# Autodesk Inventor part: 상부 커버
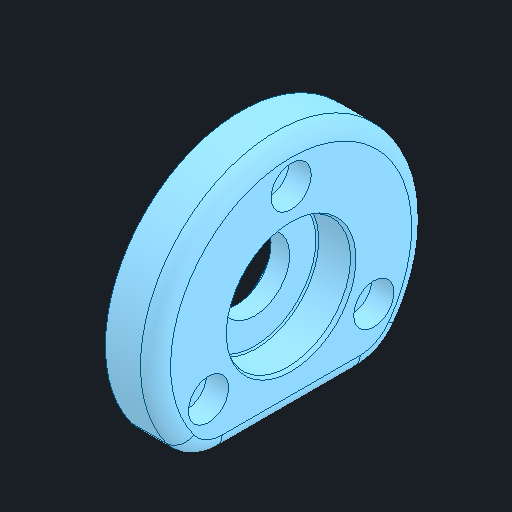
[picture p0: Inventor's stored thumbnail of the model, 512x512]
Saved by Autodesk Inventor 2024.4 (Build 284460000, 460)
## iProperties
Created: 2026-03
Part Number: 상부 커버
Material: 알루미늄 6061
Document SubType Name: Modeling
Designer: user
Density: 2.7 g/cm^3
Appearance: 기본값
Author: jhkim
Sending System: Autodesk Inventor 2026
Preprocessor: ST-DEVELOPER v20.1
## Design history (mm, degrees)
feature "솔리드1"
node "솔리드2"
